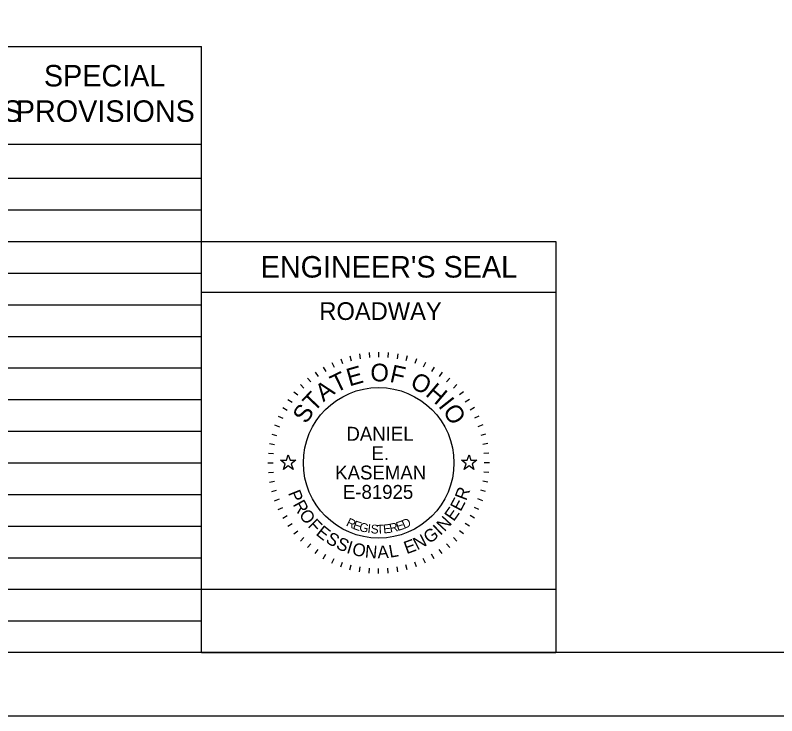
# Model space of a CAD drawing. Extents: x 0 to 34, y 0 to 22.
# Drawn here: x 22.13 to 28.15, y 0 to 5.54 of the extents above; entities that cross this region are included whole.
import ezdxf

# ---------------------------------------------------------------- set-up
doc = ezdxf.new("R2010")
doc.units = 0
for name, color, linetype in [('Default', 7, 'Continuous'), ('SH_Border', 7, 'Continuous'), ('SH_Cut_Line', 7, 'Continuous'), ('SH_Data', 7, 'Continuous'), ('SH_Text', 7, 'Continuous')]:
    doc.layers.add(name, color=color, linetype=linetype)

msp = doc.modelspace()

# ---------------------------------------------------------------- linework, layer by layer
at = {"layer": 'Default'}
for points in [[(24.2236, 2.02), (24.2705, 2.02), (24.285, 2.0645), (24.2995, 2.02), (24.3464, 2.02), (24.3085, 1.9924), (24.323, 1.9478), (24.285, 1.9754), (24.247, 1.9478), (24.2615, 1.9924)], [(25.6536, 2.02), (25.7005, 2.02), (25.715, 2.0645), (25.7295, 2.02), (25.7764, 2.02), (25.7385, 1.9924), (25.753, 1.9478), (25.715, 1.9754), (25.677, 1.9478), (25.6915, 1.9924)]]:
    msp.add_lwpolyline(points, close=True, dxfattribs=at)
at = {"layer": 'SH_Border'}
msp.add_lwpolyline([(1.5, 21.5), (33.5, 21.5), (33.5, 0.5), (1.5, 0.5)], close=True, dxfattribs=at)
at = {"layer": 'SH_Cut_Line'}
msp.add_lwpolyline([(0, 0), (34, 0), (34, 22), (0, 22)], close=True, dxfattribs=at)
at = {"layer": 'SH_Data'}
for p, q in [((10.15, 5.2917), (23.6, 5.2917)), ((23.6, 0.5), (23.6, 5.2917)), ((10.15, 4.5209), (23.6, 4.5209)), ((10.15, 4.25), (23.6, 4.25)), ((10.15, 4), (23.6, 4)), ((10.15, 3.75), (23.6, 3.75)), ((23.6, 0.5), (23.6, 3.75)), ((23.6, 3.75), (26.4, 3.75)), ((26.4, 3.75), (26.4, 0.5)), ((10.15, 3.5), (23.6, 3.5)), ((23.6, 3.35), (26.4, 3.35)), ((10.15, 3.25), (23.6, 3.25)), ((10.15, 3), (23.6, 3)), ((24.7735, 2.8452), (24.7839, 2.8065)), ((24.8481, 2.8617), (24.855, 2.8223)), ((24.9237, 2.8717), (24.9272, 2.8318)), ((25, 2.875), (25, 2.835)), ((25.0763, 2.8717), (25.0728, 2.8318)), ((25.1519, 2.8617), (25.145, 2.8223)), ((25.2265, 2.8452), (25.2161, 2.8065)), ((24.6302, 2.793), (24.6471, 2.7568)), ((24.7007, 2.8222), (24.7144, 2.7846)), ((25.2993, 2.8222), (25.2856, 2.7846)), ((25.3698, 2.793), (25.3529, 2.7568)), ((10.15, 2.75), (23.6, 2.75)), ((24.4981, 2.7168), (24.5211, 2.684)), ((24.5625, 2.7578), (24.5825, 2.7231)), ((25.4375, 2.7578), (25.4175, 2.7231)), ((25.5019, 2.7168), (25.4789, 2.684)), ((24.4376, 2.6703), (24.4633, 2.6396)), ((25.5624, 2.6703), (25.5367, 2.6396)), ((24.3813, 2.6187), (24.4096, 2.5904)), ((25.6187, 2.6187), (25.5904, 2.5904)), ((24.3297, 2.5624), (24.3604, 2.5367)), ((25.6703, 2.5624), (25.6396, 2.5367)), ((10.15, 2.5), (23.6, 2.5)), ((24.2832, 2.5019), (24.316, 2.4789)), ((25.7168, 2.5019), (25.684, 2.4789)), ((24.2422, 2.4375), (24.2769, 2.4175)), ((25.7578, 2.4375), (25.7231, 2.4175)), ((24.207, 2.3698), (24.2432, 2.3529)), ((25.793, 2.3698), (25.7568, 2.3529)), ((24.1778, 2.2993), (24.2154, 2.2856)), ((25.8222, 2.2993), (25.7846, 2.2856)), ((10.15, 2.25), (23.6, 2.25)), ((24.1548, 2.2265), (24.1935, 2.2161)), ((25.8452, 2.2265), (25.8065, 2.2161)), ((24.1383, 2.1519), (24.1777, 2.145)), ((25.8617, 2.1519), (25.8223, 2.145)), ((24.1283, 2.0763), (24.1682, 2.0728)), ((25.8717, 2.0763), (25.8318, 2.0728)), ((10.15, 2), (23.6, 2)), ((24.125, 2), (24.165, 2)), ((25.875, 2), (25.835, 2)), ((24.1283, 1.9237), (24.1682, 1.9272)), ((25.8717, 1.9237), (25.8318, 1.9272)), ((24.1383, 1.8481), (24.1777, 1.855)), ((25.8617, 1.8481), (25.8223, 1.855)), ((10.15, 1.75), (23.6, 1.75)), ((24.1548, 1.7735), (24.1935, 1.7839)), ((25.8452, 1.7735), (25.8065, 1.7839)), ((24.1778, 1.7007), (24.2154, 1.7144)), ((25.8222, 1.7007), (25.7846, 1.7144)), ((24.207, 1.6302), (24.2432, 1.6471)), ((25.793, 1.6302), (25.7568, 1.6471)), ((24.2422, 1.5625), (24.2769, 1.5825)), ((25.7578, 1.5625), (25.7231, 1.5825)), ((24.2832, 1.4981), (24.316, 1.5211)), ((25.7168, 1.4981), (25.684, 1.5211)), ((10.15, 1.5), (23.6, 1.5)), ((24.3297, 1.4376), (24.3604, 1.4633)), ((25.6703, 1.4376), (25.6396, 1.4633)), ((24.3813, 1.3813), (24.4096, 1.4096)), ((25.6187, 1.3813), (25.5904, 1.4096)), ((24.4376, 1.3297), (24.4633, 1.3604)), ((25.5624, 1.3297), (25.5367, 1.3604)), ((24.4981, 1.2832), (24.5211, 1.316)), ((24.5625, 1.2422), (24.5825, 1.2769)), ((25.4375, 1.2422), (25.4175, 1.2769)), ((25.5019, 1.2832), (25.4789, 1.316)), ((10.15, 1.25), (23.6, 1.25)), ((24.6302, 1.207), (24.6471, 1.2432)), ((24.7007, 1.1778), (24.7144, 1.2154)), ((25.2993, 1.1778), (25.2856, 1.2154)), ((25.3698, 1.207), (25.3529, 1.2432)), ((24.7735, 1.1548), (24.7839, 1.1935)), ((24.8481, 1.1383), (24.855, 1.1777)), ((24.9237, 1.1283), (24.9272, 1.1682)), ((25, 1.125), (25, 1.165)), ((25.0763, 1.1283), (25.0728, 1.1682)), ((25.1519, 1.1383), (25.145, 1.1777)), ((25.2265, 1.1548), (25.2161, 1.1935)), ((10.15, 1), (23.6, 1)), ((10.15, 0.75), (23.6, 0.75)), ((23.6, 0.5), (26.4, 0.5))]:
    msp.add_line(p, q, dxfattribs=at)
msp.add_lwpolyline([(23.6, 0.5), (23.6, 1), (26.4, 1), (26.4, 0.5)], close=True, dxfattribs=at)
msp.add_circle((25, 2), 0.595, dxfattribs=at)

# ---------------------------------------------------------------- texts
for s, height, p in [("ENGINEER'S SEAL", 0.17, (24.0676, 3.465)), ('ROADWAY', 0.14, (24.5311, 3.13)), ('DANIEL', 0.11, (24.7451, 2.1749)), ('E.', 0.11, (24.9435, 2.0216)), ('KASEMAN', 0.11, (24.6565, 1.8684)), ('E-81925', 0.11, (24.7173, 1.7151))]:
    msp.add_text(s, height=height, dxfattribs=at).set_placement(p)
for s, height, rotation, p in [('E', 0.14, 15.75706, (24.7684, 2.6038)), ('O', 0.14, 359.78119, (24.9347, 2.6443)), ('F', 0.14, 347.43619, (25.0811, 2.6417)), ('T', 0.14, 25.71674, (24.6616, 2.5518)), ('O', 0.14, 332.25863, (25.2398, 2.6015)), ('A', 0.14, 36.47472, (24.5634, 2.4781)), ('H', 0.14, 319.91363, (25.3632, 2.5361)), ('T', 0.14, 46.4344, (24.4883, 2.3964)), ('I', 0.14, 308.36695, (25.4665, 2.4483)), ('S', 0.14, 57.19238, (24.4281, 2.3014)), ('O', 0.14, 303.14906, (25.5021, 2.4089)), ('R', 0.1, 69.23216, (25.6919, 1.6954)), ('P', 0.1, 291.49398, (24.2823, 1.7621)), ('R', 0.1, 298.73106, (24.319, 1.6717)), ('E', 0.1, 61.99508, (25.6476, 1.6098)), ('O', 0.1, 306.46664, (24.3655, 1.5883)), ('E', 0.1, 54.75801, (25.5933, 1.5314)), ('N', 0.1, 47.02243, (25.5202, 1.4508)), ('F', 0.1, 314.7068, (24.4343, 1.4983)), ('E', 0.1, 321.43929, (24.4978, 1.4348)), ('R', 0.07, 334.48695, (24.7375, 1.5051)), ('E', 0.07, 341.03996, (24.7906, 1.4801)), ('G', 0.07, 347.47515, (24.8414, 1.4618)), ('I', 0.07, 353.78581, (24.9091, 1.4468)), ('S', 0.07, 356.89262, (24.9358, 1.4429)), ('T', 0.07, 3.00609, (24.9857, 1.4387)), ('E', 0.07, 6.01169, (25.0389, 1.4412)), ('R', 0.07, 11.91844, (25.0925, 1.4474)), ('E', 0.07, 17.68363, (25.1498, 1.4602)), ('D', 0.07, 23.30524, (25.201, 1.477)), ('I', 0.1, 43.28703, (25.4868, 1.4214)), ('S', 0.1, 328.67637, (24.5743, 1.3752)), ('G', 0.1, 35.04687, (25.3981, 1.357)), ('S', 0.1, 335.91345, (24.6564, 1.3266)), ('E', 0.1, 20.07421, (25.2212, 1.277)), ('N', 0.1, 27.31129, (25.3045, 1.3075)), ('I', 0.1, 343.15053, (24.7406, 1.2897)), ('O', 0.1, 346.88592, (24.7839, 1.2751)), ('N', 0.1, 355.12608, (24.8888, 1.2517)), ('A', 0.1, 2.86166, (24.9923, 1.2437)), ('L', 0.1, 10.09874, (25.0894, 1.249))]:
    msp.add_text(s, height=height, rotation=rotation, dxfattribs=at).set_placement(p)
at = {"layer": 'SH_Text'}
for s, p in [('SPECIAL', (22.3542, 4.9763)), ('SPECIFICATIONS', (20.2871, 4.6963)), ('PROVISIONS', (22.1323, 4.6963))]:
    msp.add_text(s, height=0.17, dxfattribs=at).set_placement(p)

doc.saveas('drawing.dxf')
